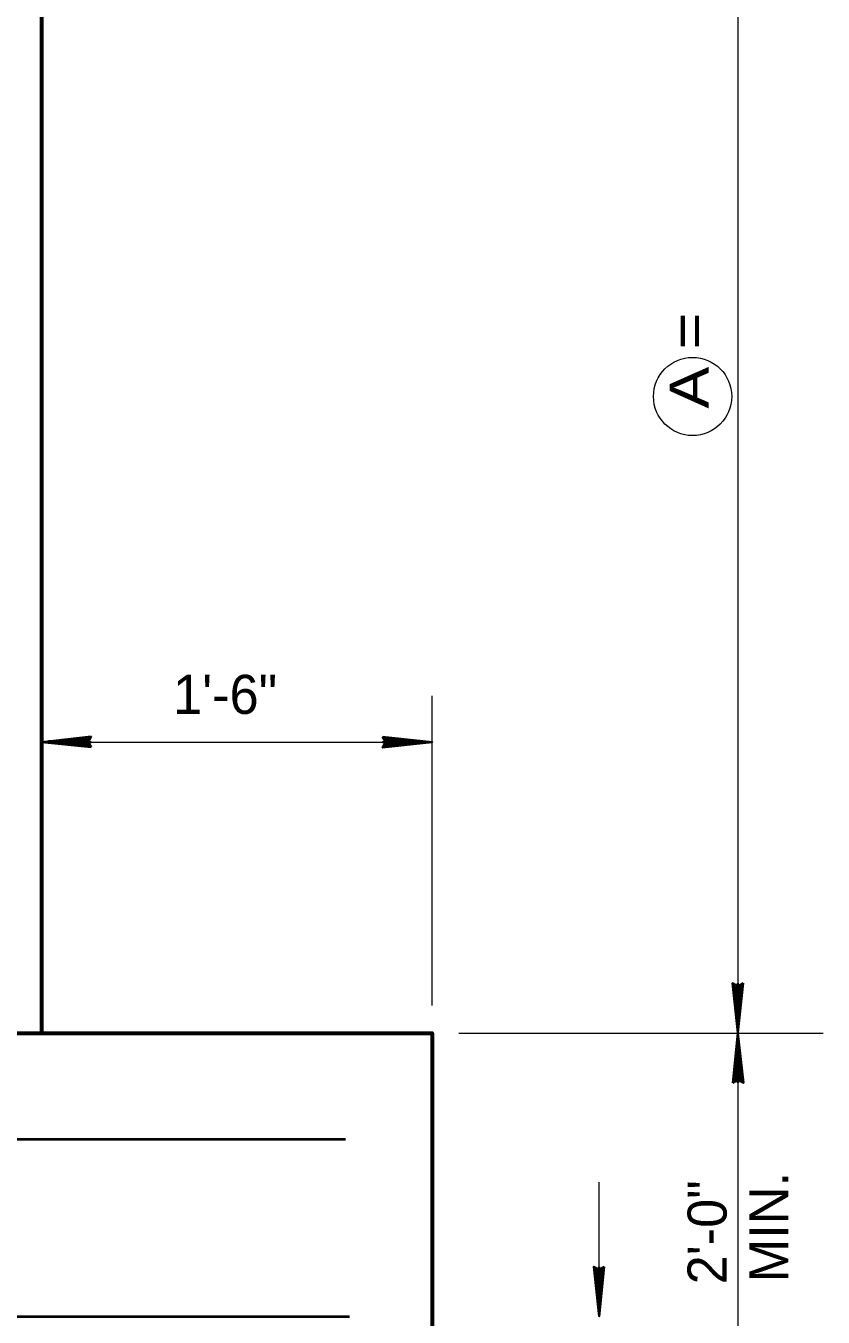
# Model space of a CAD drawing. Extents: x 14.14 to 17.34, y -1.61 to 0.38.
# Drawn here: x 15.1093 to 15.2792, y -1.2656 to -0.9903 of the extents above; entities that cross this region are included whole.
import ezdxf

# ---------------------------------------------------------------- set-up
doc = ezdxf.new("R2010")
doc.units = 0
doc.header["$LTSCALE"] = 0.0033
doc.layers.add('1', color=7, linetype='Continuous', lineweight=40)

msp = doc.modelspace()

# ---------------------------------------------------------------- linework, layer by layer
at = {"layer": '1', "lineweight": 13}
for p, q in [((15.261083, -0.873583), (15.261083, -1.288417)), ((15.195917, -1.199167), (15.195917, -1.133167)), ((15.112583, -1.143), (15.1955, -1.143)), ((15.201583, -1.205083), (15.27925, -1.205083)), ((15.2315, -1.257167), (15.2315, -1.236833))]:
    msp.add_line(p, q, dxfattribs=at)
at = {"layer": '1', "lineweight": 35}
for p, q in [((15.122917, -1.141917), (15.115583, -1.14275)), ((15.122917, -1.142083), (15.115583, -1.142833)), ((15.122917, -1.142167), (15.115583, -1.143)), ((15.185583, -1.142), (15.193417, -1.142917)), ((15.185583, -1.142), (15.193417, -1.142917)), ((15.185583, -1.142083), (15.193417, -1.142917)), ((15.185583, -1.142167), (15.193417, -1.143)), ((15.185583, -1.142167), (15.193417, -1.143167)), ((15.123167, -1.143), (15.112583, -1.143)), ((15.122917, -1.143833), (15.115083, -1.142833)), ((15.122917, -1.143833), (15.115083, -1.143)), ((15.122917, -1.144), (15.115083, -1.143083)), ((15.122917, -1.144), (15.115083, -1.143083)), ((15.122917, -1.143917), (15.115083, -1.143083)), ((15.123, -1.142333), (15.115667, -1.143083)), ((15.185333, -1.143), (15.195917, -1.143)), ((15.1855, -1.143667), (15.192833, -1.142917)), ((15.185583, -1.143833), (15.192917, -1.143)), ((15.185583, -1.143917), (15.192917, -1.143167)), ((15.185583, -1.144083), (15.192917, -1.14325)), ((15.260417, -1.194583), (15.261167, -1.201917)), ((15.261083, -1.194417), (15.261083, -1.205)), ((15.26, -1.194667), (15.260833, -1.202)), ((15.260167, -1.194667), (15.260917, -1.202)), ((15.26025, -1.194667), (15.261083, -1.202)), ((15.261917, -1.194667), (15.260917, -1.2025)), ((15.261917, -1.194667), (15.261083, -1.2025)), ((15.262083, -1.194667), (15.261167, -1.2025)), ((15.262083, -1.194667), (15.261167, -1.2025)), ((15.262, -1.194667), (15.261167, -1.2025)), ((15.261083, -1.215667), (15.261083, -1.205083)), ((15.260083, -1.215417), (15.261, -1.207583)), ((15.260083, -1.215417), (15.261, -1.207583)), ((15.260167, -1.215417), (15.261, -1.207583)), ((15.26025, -1.215417), (15.261083, -1.207583)), ((15.26025, -1.215417), (15.26125, -1.207583)), ((15.26175, -1.2155), (15.261, -1.208167)), ((15.261917, -1.215417), (15.261083, -1.208083)), ((15.262, -1.215417), (15.26125, -1.208083)), ((15.262167, -1.215417), (15.261333, -1.208083)), ((15.230417, -1.255083), (15.23125, -1.262417)), ((15.230583, -1.255083), (15.231333, -1.262417)), ((15.230667, -1.255083), (15.2315, -1.262417)), ((15.230833, -1.255), (15.231583, -1.262333)), ((15.232333, -1.255083), (15.231333, -1.262917)), ((15.2315, -1.254833), (15.2315, -1.265417)), ((15.232333, -1.255083), (15.2315, -1.262917)), ((15.2325, -1.255083), (15.231583, -1.262917)), ((15.2325, -1.255083), (15.231583, -1.262917)), ((15.232417, -1.255083), (15.231583, -1.262917))]:
    msp.add_line(p, q, dxfattribs=at)
at = {"layer": '1', "lineweight": 60}
for points in [[(15.112583, -0.87175), (15.112583, -1.205083), (15.195917, -1.205083), (15.195917, -1.288417)], [(14.52925, -1.205083), (14.772417, -1.205083), (15.112583, -1.205083)]]:
    msp.add_lwpolyline(points, dxfattribs=at)
at = {"layer": '1', "lineweight": 35}
for points in [[(15.123167, -1.144083), (15.112583, -1.143), (15.123167, -1.141833), (15.122583, -1.143)], [(15.185333, -1.141917), (15.195917, -1.143), (15.185333, -1.144167), (15.185917, -1.143)], [(15.122417, -1.143083), (15.11775, -1.143167), (15.11775, -1.143083), (15.118667, -1.143083), (15.122417, -1.143167), (15.119417, -1.14325), (15.122583, -1.143333), (15.120333, -1.143417), (15.122583, -1.1435), (15.119083, -1.14325), (15.114417, -1.143083), (15.115333, -1.142833), (15.114083, -1.142833), (15.122417, -1.142833), (15.12, -1.142667), (15.122583, -1.142667), (15.11725, -1.143083), (15.122583, -1.142417)], [(15.186083, -1.142917), (15.19075, -1.142833), (15.19075, -1.142917), (15.189833, -1.142917), (15.186083, -1.142833), (15.189083, -1.14275), (15.185917, -1.142667), (15.188167, -1.142583), (15.185917, -1.1425), (15.189417, -1.14275), (15.194083, -1.142917), (15.193167, -1.143167), (15.194417, -1.143167), (15.186083, -1.143167), (15.1885, -1.143333), (15.185917, -1.143333), (15.19125, -1.142917), (15.185917, -1.143583)], [(15.262167, -1.194417), (15.261083, -1.205), (15.259917, -1.194417), (15.261083, -1.195)], [(15.261167, -1.195167), (15.26125, -1.199833), (15.261167, -1.199833), (15.261167, -1.198917), (15.26125, -1.195167), (15.261333, -1.198167), (15.261417, -1.195), (15.2615, -1.19725), (15.261583, -1.195), (15.261333, -1.1985), (15.261167, -1.203167), (15.260917, -1.20225), (15.260917, -1.2035), (15.260917, -1.195167), (15.26075, -1.197583), (15.26075, -1.195), (15.261167, -1.200333), (15.2605, -1.195)], [(15.26, -1.215667), (15.261083, -1.205083), (15.26225, -1.215667), (15.261083, -1.215083)], [(15.261, -1.214917), (15.260917, -1.21025), (15.261, -1.21025), (15.261, -1.211167), (15.260917, -1.214917), (15.260833, -1.211917), (15.26075, -1.215083), (15.260667, -1.212833), (15.260583, -1.215083), (15.260833, -1.211583), (15.261, -1.206917), (15.26125, -1.207833), (15.26125, -1.206583), (15.26125, -1.214917), (15.261417, -1.2125), (15.261417, -1.215083), (15.261, -1.20975), (15.261667, -1.215083)], [(15.232583, -1.254833), (15.2315, -1.265417), (15.230333, -1.254833), (15.2315, -1.255417)], [(15.231583, -1.255583), (15.231667, -1.26025), (15.231583, -1.26025), (15.231583, -1.259333), (15.231667, -1.255583), (15.23175, -1.258583), (15.231833, -1.255417), (15.231917, -1.257667), (15.232, -1.255417), (15.23175, -1.258917), (15.231583, -1.263583), (15.231333, -1.262667), (15.231333, -1.263917), (15.231333, -1.255583), (15.231167, -1.258), (15.231167, -1.255417), (15.231583, -1.26075), (15.230917, -1.255417)]]:
    msp.add_lwpolyline(points, close=True, dxfattribs=at)
for points in [[(15.122417, -1.143083), (15.122833, -1.143833), (15.122583, -1.143583), (15.122417, -1.14325), (15.122167, -1.143333), (15.122333, -1.143667), (15.1225, -1.142917), (15.122667, -1.142417), (15.122917, -1.142)], [(15.186083, -1.142917), (15.185667, -1.142167), (15.185917, -1.142417), (15.186083, -1.14275), (15.186333, -1.142667), (15.186167, -1.142333), (15.186, -1.143083), (15.185833, -1.143583), (15.185583, -1.144)], [(15.261167, -1.195167), (15.261917, -1.19475), (15.261667, -1.195), (15.261333, -1.195167), (15.261417, -1.195417), (15.26175, -1.19525), (15.261, -1.195083), (15.2605, -1.194917), (15.260083, -1.194667)], [(15.261, -1.214917), (15.26025, -1.215333), (15.2605, -1.215083), (15.260833, -1.214917), (15.26075, -1.214667), (15.260417, -1.214833), (15.261167, -1.215), (15.261667, -1.215167), (15.262083, -1.215417)], [(15.231583, -1.255583), (15.232333, -1.255167), (15.232083, -1.255417), (15.23175, -1.255583), (15.231833, -1.255833), (15.232167, -1.255667), (15.231417, -1.2555), (15.230917, -1.255333), (15.2305, -1.255083)]]:
    msp.add_lwpolyline(points, dxfattribs=at)
at = {"layer": '1'}
for points in [[(14.772417, -1.2235), (14.83475, -1.2235), (14.842, -1.227667), (15.177417, -1.227667)], [(14.7725, -1.26125), (14.834083, -1.26125), (14.841333, -1.265417), (15.17825, -1.265417)]]:
    msp.add_lwpolyline(points, dxfattribs=at)
at = {"layer": '1', "lineweight": 13}
msp.add_circle((15.251417, -1.069333), 0.008333, dxfattribs=at)

# ---------------------------------------------------------------- texts
at = {"layer": '1', "width": 1.2}
msp.add_text('A =      ', height=0.008334, rotation=90, dxfattribs=at).set_placement((15.254833, -1.071917))
at = {"layer": '1'}
msp.add_text('1\'-6"', height=0.008334, dxfattribs=at).set_placement((15.140667, -1.137))
for s, height, p in [('MIN.', 0.008334, (15.271833, -1.258167)), ('2\'-0"', 0.008333, (15.258667, -1.258583))]:
    msp.add_text(s, height=height, rotation=90, dxfattribs=at).set_placement(p)

doc.saveas('drawing.dxf')
